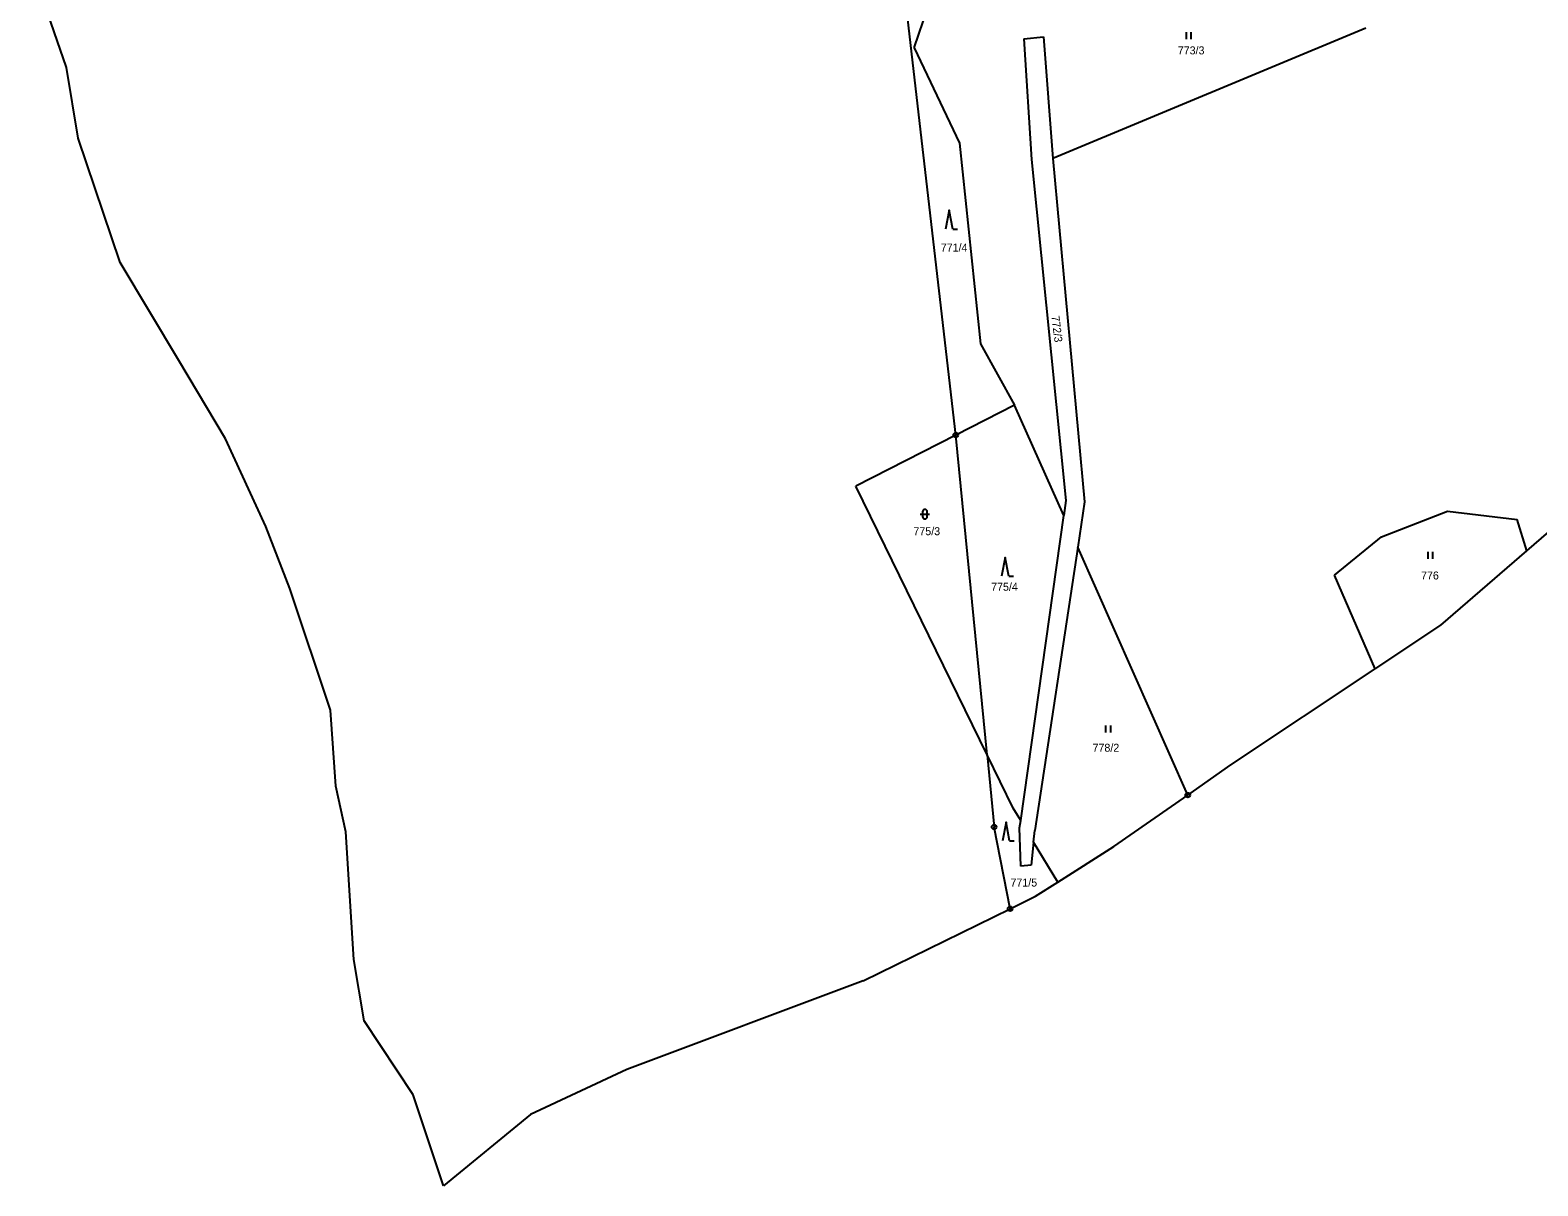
# Model space of a CAD drawing. Extents: x -754970 to -752637, y -970569 to -968179.
# Drawn here: x -754476.3 to -754155, y -970569.3 to -970322.9 of the extents above; entities that cross this region are included whole.
import ezdxf
from ezdxf.enums import TextEntityAlignment as Align

# ---------------------------------------------------------------- set-up
doc = ezdxf.new("R2010")
doc.units = 0
doc.header["$LTSCALE"] = 0.68
for name, color, linetype, lineweight in [('1', 7, 'Continuous', 25), ('3', 7, 'Continuous', 25), ('8', 7, 'Continuous', 25)]:
    doc.layers.add(name, color=color, linetype=linetype, lineweight=lineweight)
doc.layers.add('2', color=7, linetype='Continuous')

msp = doc.modelspace()

# ---------------------------------------------------------------- linework, layer by layer
at = {"layer": '1'}
for p, q in [((-754468.5, -970330.9), (-754476.28, -970308.62)), ((-754279.06, -970409.25), (-754289.51, -970318.8)), ((-754287.93, -970326.74), (-754285, -970318.19)), ((-754191.69, -970322.5), (-754258.35, -970350.29)), ((-754287.93, -970326.74), (-754278.26, -970347.05)), ((-754264.52, -970324.78), (-754260.39, -970324.35)), ((-754264.52, -970324.78), (-754262.93, -970350.54)), ((-754260.39, -970324.35), (-754258.35, -970350.29)), ((-754466.03, -970345.98), (-754468.5, -970330.9)), ((-754457.1, -970372.46), (-754466.03, -970345.98)), ((-754278.26, -970347.05), (-754273.8, -970389.81)), ((-754262.93, -970350.54), (-754255.58, -970423.21)), ((-754258.35, -970350.29), (-754251.6, -970423.5)), ((-754444.57, -970393.35), (-754457.1, -970372.46)), ((-754273.8, -970389.81), (-754266.56, -970402.89)), ((-754434.64, -970410.03), (-754444.57, -970393.35)), ((-754266.56, -970402.89), (-754279.06, -970409.25)), ((-754256.03, -970426.37), (-754266.56, -970402.89)), ((-754426.03, -970428.74), (-754434.64, -970410.03)), ((-754279.06, -970409.25), (-754300.36, -970420.13)), ((-754272.39, -970477.38), (-754279.06, -970409.25)), ((-754272.39, -970477.38), (-754300.36, -970420.13)), ((-754255.58, -970423.21), (-754256.03, -970426.37)), ((-754251.6, -970423.5), (-754253.04, -970433.13)), ((-754265.22, -970491.42), (-754256.03, -970426.37)), ((-754188.35, -970430.93), (-754174.29, -970425.45)), ((-754174.29, -970425.45), (-754159.4, -970427.26)), ((-754420.92, -970441.93), (-754426.03, -970428.74)), ((-754157.34, -970433.89), (-754159.4, -970427.26)), ((-754157.34, -970433.89), (-754152.7, -970429.89)), ((-754253.04, -970433.13), (-754262.18, -970493.52)), ((-754229.63, -970485.99), (-754253.04, -970433.13)), ((-754198.32, -970439.1), (-754188.35, -970430.93)), ((-754175.72, -970449.78), (-754157.34, -970433.89)), ((-754189.65, -970459.07), (-754198.32, -970439.1)), ((-754412.3, -970467.92), (-754420.92, -970441.93)), ((-754189.65, -970459.07), (-754175.72, -970449.78)), ((-754220.41, -970479.57), (-754189.65, -970459.07)), ((-754411.17, -970484.1), (-754412.3, -970467.92)), ((-754272.39, -970477.38), (-754270.88, -970492.79)), ((-754266.83, -970488.76), (-754272.39, -970477.38)), ((-754229.63, -970485.99), (-754220.41, -970479.57)), ((-754409, -970493.79), (-754411.17, -970484.1)), ((-754245.35, -970496.92), (-754229.63, -970485.99)), ((-754265.22, -970491.42), (-754266.83, -970488.76)), ((-754407.3, -970521.01), (-754409, -970493.79)), ((-754267.47, -970510.2), (-754270.88, -970492.79)), ((-754265.44, -970492.95), (-754265.22, -970491.42)), ((-754265.21, -970501.13), (-754265.44, -970492.95)), ((-754262.46, -970496.01), (-754262.18, -970493.52)), ((-754262.46, -970496.01), (-754263.01, -970500.92)), ((-754257.32, -970504.53), (-754262.46, -970496.01)), ((-754257.32, -970504.53), (-754245.35, -970496.92)), ((-754263.01, -970500.92), (-754265.21, -970501.13)), ((-754262.05, -970507.54), (-754257.32, -970504.53)), ((-754298.75, -970525.58), (-754267.47, -970510.2)), ((-754267.47, -970510.2), (-754262.05, -970507.54)), ((-754405.11, -970534.08), (-754407.3, -970521.01)), ((-754298.75, -970525.58), (-754349.12, -970544.48)), ((-754394.67, -970549.85), (-754405.11, -970534.08)), ((-754349.12, -970544.48), (-754369.68, -970554.05)), ((-754388.23, -970569.28), (-754394.67, -970549.85)), ((-754369.68, -970554.05), (-754388.23, -970569.28))]:
    msp.add_line(p, q, dxfattribs=at)
at = {"layer": '3'}
for p, q in [((-754229.871, -970324.88), (-754229.871, -970323.38)), ((-754228.87, -970324.88), (-754228.87, -970323.38)), ((-754279.71, -970365.33), (-754278.714, -970365.33)), ((-754286.641, -970426.111), (-754284.639, -970426.111)), ((-754286.141, -970425.611), (-754286.141, -970426.612)), ((-754285.139, -970426.612), (-754285.139, -970425.611)), ((-754178.381, -970435.61), (-754178.381, -970434.11)), ((-754177.38, -970435.61), (-754177.38, -970434.11)), ((-754267.77, -970439.34), (-754266.774, -970439.34)), ((-754247.041, -970472.68), (-754247.041, -970471.18)), ((-754246.04, -970472.68), (-754246.04, -970471.18)), ((-754267.58, -970495.77), (-754266.584, -970495.77))]:
    msp.add_line(p, q, dxfattribs=at)
for points in [[(-754279.71, -970365.33), (-754280.46, -970361.33), (-754281.21, -970365.33)], [(-754267.77, -970439.34), (-754268.52, -970435.34), (-754269.27, -970439.34)], [(-754267.58, -970495.77), (-754268.33, -970491.77), (-754269.08, -970495.77)]]:
    msp.add_lwpolyline(points, dxfattribs=at)
for centre, start, end in [((-754285.64, -970425.6109), 0, 180), ((-754285.64, -970426.6109), 180, 359.98789)]:
    msp.add_arc(centre, 0.5, start, end, dxfattribs=at)
at = {"layer": '8'}
for centre, radius in [((-754279.06, -970409.2499), 0.5), ((-754279.06, -970409.2499), 0.0303), ((-754229.63, -970485.9899), 0.5), ((-754229.63, -970485.9899), 0.0303), ((-754270.88, -970492.7899), 0.5), ((-754270.88, -970492.7899), 0.0303), ((-754267.47, -970510.1999), 0.5), ((-754267.47, -970510.1999), 0.0303)]:
    msp.add_circle(centre, radius, dxfattribs=at)

# ---------------------------------------------------------------- texts
at = {"layer": '2'}
for s, p in [('773/3', (-754228.9, -970328.105)), ('771/4', (-754279.4, -970370.125)), ('775/3', (-754285.23, -970430.595)), ('776', (-754178.009, -970440.035)), ('775/4', (-754268.67, -970442.435)), ('778/2', (-754247.06, -970476.745)), ('771/5', (-754264.55, -970505.485))]:
    msp.add_text(s, height=1.7, dxfattribs=at).set_placement(p, align=Align.CENTER)
msp.add_text('772/3', height=1.7, rotation=277, dxfattribs=at).set_placement((-754258.3249, -970386.7339), align=Align.CENTER)

doc.saveas('drawing.dxf')
